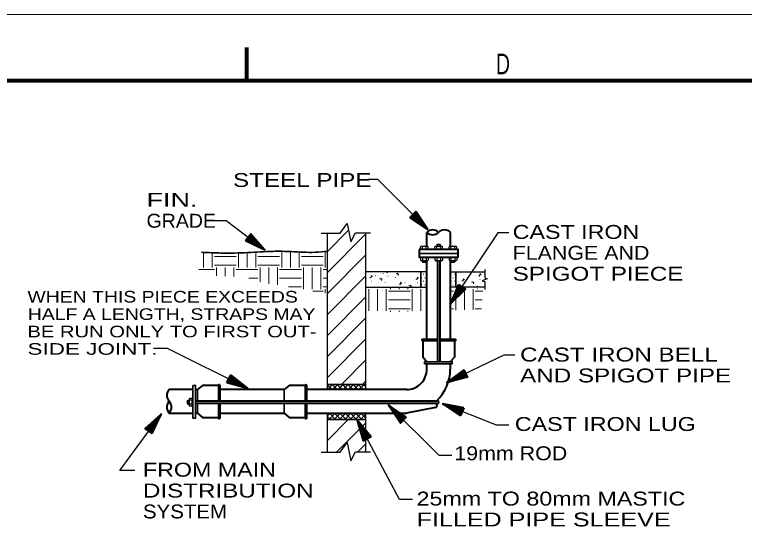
# Model space of a CAD drawing. Extents: x 55 to 190, y 198 to 264.
# Drawn here: x 89.01 to 102.33, y 248.35 to 257.85 of the extents above; entities that cross this region are included whole.
import ezdxf
from ezdxf.enums import TextEntityAlignment as Align

# ---------------------------------------------------------------- set-up
doc = ezdxf.new("R2010")
doc.units = 0
doc.header["$LTSCALE"] = 0.1
doc.layers.add('1', color=7, linetype='Continuous', lineweight=25)
doc.layers.add('2', color=7, linetype='Continuous', lineweight=40)

msp = doc.modelspace()

# ---------------------------------------------------------------- linework, layer by layer
at = {"layer": '1', "lineweight": 80}
msp.add_line((93.2427, 257.2525), (93.2427, 256.6525), dxfattribs=at)
at = {"layer": '1', "lineweight": 13}
msp.add_lwpolyline([(62.4915, 257.8525), (146.5927, 257.8525), (146.5927, 198.4512), (62.4915, 198.4512)], close=True, dxfattribs=at)
at = {"layer": '1', "lineweight": 80}
msp.add_lwpolyline([(65.1915, 256.6525), (145.3927, 256.6525), (145.3927, 199.6512), (65.1915, 199.6512)], close=True, dxfattribs=at)
at = {"layer": '2'}
for p, q in [((96.5497, 253.9364), (96.2539, 254.1822)), ((96.5497, 253.9364), (96.2663, 254.1939)), ((96.2788, 254.2066), (96.5497, 253.9364)), ((96.5497, 253.9364), (96.2925, 254.22)), ((96.5497, 253.9364), (96.319, 254.2465)), ((96.5497, 253.9364), (96.2391, 254.1666)), ((93.2729, 253.7928), (93.5769, 253.5602)), ((93.5769, 253.5602), (93.2848, 253.8078)), ((93.5769, 253.5602), (93.3075, 253.8375)), ((96.5354, 253.6266), (96.5354, 253.8803)), ((96.9622, 253.8803), (96.9622, 253.6266)), ((93.5769, 253.5602), (93.239, 253.748)), ((93.5769, 253.5602), (93.2514, 253.7652)), ((93.5769, 253.5602), (93.2623, 253.7785)), ((96.5354, 251.9311), (96.5354, 253.3652)), ((96.7302, 253.3636), (96.7302, 251.5184)), ((96.7802, 251.5184), (96.7802, 253.3636)), ((96.9622, 253.3636), (96.9622, 251.9311)), ((96.9638, 252.5691), (97.1278, 252.9191)), ((96.9638, 252.5691), (97.1461, 252.9077)), ((96.9638, 252.5691), (97.1599, 252.8979)), ((97.1749, 252.8881), (96.9638, 252.5691)), ((96.9638, 252.5691), (97.1908, 252.8773)), ((96.9638, 252.5691), (97.2218, 252.8566)), ((96.5354, 251.385), (96.5354, 251.4845)), ((96.9622, 251.4845), (96.9622, 251.385)), ((93.2631, 251.0387), (92.9453, 251.2586)), ((96.9011, 251.139), (97.221, 251.3562)), ((96.9011, 251.139), (97.2308, 251.3372)), ((96.9011, 251.139), (97.2376, 251.3215)), ((97.2456, 251.3057), (96.9011, 251.139)), ((96.9011, 251.139), (97.2538, 251.2882)), ((96.9011, 251.139), (97.2699, 251.2546)), ((93.2631, 251.0387), (92.8953, 251.1578)), ((93.2631, 251.0387), (92.9043, 251.1771)), ((93.2631, 251.0387), (92.9122, 251.1922)), ((92.9199, 251.2083), (93.2631, 251.0387)), ((93.2631, 251.0387), (92.9286, 251.2252)), ((92.2645, 251.0109), (91.8319, 251.0109)), ((93.9309, 251.0109), (92.7606, 251.0109)), ((96.17, 251.0109), (94.3439, 251.0109)), ((92.3124, 250.8085), (96.7257, 250.8085)), ((96.7257, 250.7553), (92.3151, 250.7553)), ((96.1076, 250.4569), (95.8348, 250.7252)), ((95.8348, 250.7252), (96.1322, 250.4815)), ((95.8348, 250.7252), (96.0677, 250.4167)), ((95.8348, 250.7252), (96.0938, 250.4434)), ((95.8348, 250.7252), (96.12, 250.4696)), ((95.8348, 250.7252), (96.147, 250.4971)), ((97.1815, 250.6096), (96.8257, 250.7503)), ((96.8257, 250.7503), (97.1945, 250.6418)), ((96.8257, 250.7503), (97.1604, 250.5572)), ((96.8257, 250.7503), (97.1741, 250.5918)), ((96.8257, 250.7503), (97.1879, 250.6262)), ((96.8257, 250.7503), (97.2019, 250.6619)), ((91.8319, 250.5839), (92.2645, 250.5839)), ((92.7612, 250.5839), (93.9309, 250.5839)), ((94.3439, 250.5839), (96.1613, 250.5839)), ((96.6955, 250.6879), (96.1613, 250.5839)), ((91.6827, 250.5619), (91.4118, 250.2865)), ((91.6827, 250.5619), (91.4417, 250.2643)), ((91.457, 250.2529), (91.6827, 250.5619)), ((91.6827, 250.5619), (91.4716, 250.2426)), ((91.6827, 250.5619), (91.4851, 250.232)), ((91.6827, 250.5619), (91.5028, 250.2198)), ((95.4499, 250.1113), (95.2702, 250.4492)), ((95.2702, 250.4492), (95.4808, 250.1275)), ((95.2702, 250.4492), (95.3998, 250.0852)), ((95.2702, 250.4492), (95.4329, 250.1026)), ((95.2702, 250.4492), (95.4657, 250.1201)), ((95.2702, 250.4492), (95.4996, 250.1381))]:
    msp.add_line(p, q, dxfattribs=at)
at = {"layer": '2', "lineweight": 13}
for p, q in [((94.7209, 253.5332), (95.1054, 253.9176)), ((94.7212, 253.1501), (95.4178, 253.847)), ((93.888, 253.2414), (93.888, 253.5184)), ((94.0468, 253.2414), (94.0468, 253.5189)), ((94.2055, 253.2414), (94.2055, 253.5216)), ((92.4593, 253.2414), (92.4593, 253.4988)), ((92.618, 253.2414), (92.618, 253.4988)), ((92.6577, 253.4398), (93.0546, 253.4398)), ((93.0943, 253.2414), (93.0943, 253.4946)), ((93.253, 253.2414), (93.253, 253.5028)), ((93.4118, 253.2414), (93.4118, 253.5107)), ((93.4515, 253.4398), (93.8483, 253.4398)), ((94.2452, 253.4398), (94.6421, 253.4398)), ((94.6818, 253.2414), (94.6818, 253.512)), ((94.7212, 252.767), (95.4178, 253.4639)), ((92.6577, 253.2811), (93.0546, 253.2811)), ((93.4515, 253.2811), (93.8483, 253.2811)), ((94.2452, 253.2811), (94.6421, 253.2811)), ((92.3712, 253.2017), (92.6577, 253.2017)), ((92.6974, 253.0858), (92.6974, 253.2414)), ((92.8561, 253.081), (92.8561, 253.2414)), ((93.0149, 253.076), (93.0149, 253.2414)), ((93.0546, 253.2017), (93.4515, 253.2017)), ((93.4911, 252.9805), (93.4911, 253.2414)), ((93.6499, 252.9432), (93.6499, 253.2414)), ((93.8086, 252.9215), (93.8086, 253.2414)), ((93.8483, 253.2017), (94.2452, 253.2017)), ((94.2849, 252.8445), (94.2849, 253.2414)), ((94.4436, 252.8445), (94.4436, 253.2414)), ((94.6024, 252.8445), (94.6024, 253.2414)), ((94.6421, 253.2017), (94.7024, 253.2017)), ((95.7377, 253.1302), (95.7382, 253.1329)), ((95.8007, 253.1498), (95.8311, 253.1591)), ((95.82, 253.1601), (95.8152, 253.1395)), ((96.0044, 253.1353), (95.974, 253.126)), ((95.9901, 253.1334), (96.0131, 253.112)), ((96.0118, 253.0943), (96.019, 253.1252)), ((96.2669, 253.1511), (96.265, 253.153)), ((96.3822, 253.1498), (96.3817, 253.1472)), ((96.4677, 253.1144), (96.4783, 253.1144)), ((96.5312, 253.1144), (96.5317, 253.1144)), ((96.976, 253.1144), (96.9863, 253.1144)), ((97.0392, 253.1144), (97.05, 253.1144)), ((97.1067, 253.1207), (97.1048, 253.1223)), ((97.1556, 253.1559), (97.1569, 253.1615)), ((97.2223, 253.1189), (97.2218, 253.1162)), ((97.5266, 253.1054), (97.5033, 253.1271)), ((97.5811, 253.1186), (97.584, 253.1194)), ((93.2885, 253.0429), (93.4515, 253.0429)), ((93.8483, 253.0429), (94.2452, 253.0429)), ((94.6421, 253.0429), (94.7024, 253.0429)), ((94.7212, 252.3841), (95.4178, 253.0808)), ((95.434, 253.0376), (95.4345, 253.04)), ((95.4972, 253.057), (95.5274, 253.0662)), ((95.5184, 253.0776), (95.5112, 253.0469)), ((95.5432, 253.0736), (95.5202, 253.095)), ((95.5237, 252.9882), (95.521, 252.9874)), ((95.5983, 253.0879), (95.6015, 253.0887)), ((95.7007, 253.0424), (95.6702, 253.0331)), ((95.6864, 253.0405), (95.7094, 253.0189)), ((95.7081, 253.0014), (95.7152, 253.0323)), ((95.8271, 253.081), (95.8248, 253.0802)), ((95.9631, 253.0583), (95.9613, 253.0601)), ((96.0785, 253.057), (96.078, 253.0546)), ((96.274, 253.0064), (96.2746, 253.0091)), ((96.3367, 253.0257), (96.3669, 253.035)), ((96.3584, 253.0466), (96.3513, 253.0157)), ((96.383, 253.0429), (96.3598, 253.0646)), ((96.436, 253.0509), (96.4465, 253.0509)), ((96.4677, 252.9874), (96.4783, 252.9874)), ((96.4995, 253.0509), (96.51, 253.0509)), ((96.5312, 252.9874), (96.532, 252.9874)), ((96.976, 252.9874), (96.9863, 252.9874)), ((97.0075, 253.0509), (97.018, 253.0509)), ((97.0392, 252.9874), (97.05, 252.9874)), ((97.1763, 252.9948), (97.2064, 253.004)), ((97.1985, 253.0157), (97.1913, 252.9847)), ((97.2228, 253.0122), (97.1995, 253.0339)), ((97.2773, 253.0257), (97.2805, 253.0265)), ((97.4178, 253.0683), (97.4183, 253.0707)), ((97.4797, 253.0876), (97.5102, 253.0969)), ((97.5025, 253.1085), (97.4953, 253.0776)), ((97.5062, 253.0189), (97.5038, 253.0181)), ((94.0124, 252.8842), (94.2452, 252.8842)), ((94.6421, 252.8842), (94.7024, 252.8842)), ((95.6594, 252.9651), (95.6575, 252.967)), ((95.7748, 252.9643), (95.7742, 252.9617)), ((95.8724, 252.8445), (95.8724, 252.8691)), ((95.97, 252.9138), (95.9708, 252.9162)), ((96.0311, 252.8445), (96.0311, 252.8704)), ((96.033, 252.9329), (96.0634, 252.9424)), ((96.0547, 252.954), (96.0475, 252.9231)), ((96.0793, 252.9501), (96.056, 252.9715)), ((96.1341, 252.9638), (96.1372, 252.9649)), ((96.1899, 252.8445), (96.1899, 252.8717)), ((96.2367, 252.9186), (96.2063, 252.9093)), ((96.2222, 252.917), (96.2455, 252.8953)), ((96.2447, 252.8794), (96.2513, 252.9085)), ((96.3632, 252.9572), (96.3605, 252.9564)), ((96.436, 252.9239), (96.4465, 252.9239)), ((96.4995, 252.9239), (96.51, 252.9239)), ((97.0075, 252.9239), (97.018, 252.9239)), ((97.1141, 252.9754), (97.1146, 252.9781)), ((97.2027, 252.9262), (97.2001, 252.9255)), ((97.339, 252.904), (97.3371, 252.9059)), ((97.3797, 252.9802), (97.3493, 252.971)), ((97.3657, 252.9794), (97.389, 252.9577)), ((97.3882, 252.9395), (97.3953, 252.9702)), ((97.4549, 252.9022), (97.4543, 252.8995)), ((94.4558, 252.8048), (94.6421, 252.8048)), ((94.6818, 252.7797), (94.6818, 252.8445)), ((95.4337, 252.8048), (95.4358, 252.8048)), ((95.4755, 252.4476), (95.4755, 252.8445)), ((95.6343, 252.4476), (95.6343, 252.8445)), ((95.793, 252.4476), (95.793, 252.8445)), ((95.8327, 252.8048), (96.2296, 252.8048)), ((96.2693, 252.4476), (96.2693, 252.8445)), ((96.428, 252.4476), (96.428, 252.8445)), ((96.9855, 252.8048), (97.0233, 252.8048)), ((97.063, 252.4579), (97.063, 252.8445)), ((97.2218, 252.4638), (97.2218, 252.8445)), ((97.3808, 252.4696), (97.3808, 252.8445)), ((97.4202, 252.8048), (97.5565, 252.8048)), ((97.4599, 252.8445), (97.4599, 252.8471)), ((94.7212, 252.001), (95.4178, 252.6976)), ((95.4337, 252.6461), (95.4358, 252.6461)), ((95.8327, 252.6461), (96.2296, 252.6461)), ((96.9895, 252.6461), (97.0233, 252.6461)), ((97.4202, 252.6461), (97.544, 252.6461)), ((95.4337, 252.4873), (95.4358, 252.4873)), ((95.8327, 252.4873), (96.2296, 252.4873)), ((96.9934, 252.4873), (97.0233, 252.4873)), ((97.4202, 252.4873), (97.5313, 252.4873)), ((95.8724, 252.4283), (95.8724, 252.4476)), ((96.0311, 252.4325), (96.0311, 252.4476)), ((96.1899, 252.4368), (96.1899, 252.4476)), ((94.7215, 251.6179), (95.4178, 252.3143)), ((94.7215, 251.2348), (95.4181, 251.9311)), ((94.9892, 251.1191), (95.4181, 251.548)), ((95.3649, 251.1117), (95.4181, 251.1649)), ((94.7209, 251.0136), (94.8143, 251.1067)), ((94.8053, 251.0109), (94.7212, 251.0948)), ((94.9011, 251.0109), (94.8051, 251.1067)), ((94.8141, 251.0109), (94.9101, 251.1067)), ((94.9969, 251.0109), (94.9008, 251.1067)), ((94.9098, 251.0109), (95.0059, 251.1067)), ((95.0927, 251.0109), (94.9969, 251.1067)), ((95.0059, 251.0109), (95.1017, 251.1067)), ((95.1884, 251.0109), (95.0927, 251.1067)), ((95.1017, 251.0109), (95.1974, 251.1067)), ((95.2842, 251.0109), (95.1884, 251.1067)), ((95.1974, 251.0109), (95.2932, 251.1067)), ((95.38, 251.0109), (95.2842, 251.1067)), ((95.2932, 251.0109), (95.389, 251.1067)), ((95.4178, 251.0686), (95.38, 251.1067)), ((95.389, 251.0109), (95.4178, 251.04)), ((94.7212, 250.5347), (94.7675, 250.581)), ((94.7741, 250.4672), (94.7212, 250.5201)), ((94.7212, 250.0849), (95.1056, 250.4696)), ((94.7495, 250.4672), (94.8633, 250.581)), ((94.8699, 250.4672), (94.7561, 250.581)), ((94.8453, 250.4672), (94.959, 250.581)), ((94.9657, 250.4672), (94.8519, 250.581)), ((94.9411, 250.4672), (95.0548, 250.581)), ((95.0614, 250.4672), (94.9477, 250.581)), ((95.0368, 250.4672), (95.1506, 250.581)), ((95.1572, 250.4672), (95.0435, 250.581)), ((95.1326, 250.4672), (95.2464, 250.581)), ((95.253, 250.4672), (95.1392, 250.581)), ((95.2284, 250.4672), (95.3422, 250.581)), ((95.3488, 250.4672), (95.235, 250.581)), ((95.3242, 250.4672), (95.4178, 250.5609)), ((95.4178, 250.4939), (95.3308, 250.581)), ((94.8945, 249.8751), (95.4181, 250.3987)), ((95.2771, 249.8745), (95.4178, 250.0153))]:
    msp.add_line(p, q, dxfattribs=at)
at = {"layer": '2', "lineweight": 25}
for p, q in [((94.7209, 251.0109), (94.7209, 253.8687)), ((95.4178, 253.8687), (95.4178, 251.0109)), ((96.4206, 253.5673), (96.4206, 253.6158)), ((96.4206, 253.5673), (96.5598, 253.5673)), ((96.4381, 253.6266), (96.5423, 253.6266)), ((96.4553, 253.5673), (96.4553, 253.6158)), ((96.5251, 253.5673), (96.5251, 253.6158)), ((96.5598, 253.5673), (96.5598, 253.6155)), ((96.6825, 253.5673), (96.6825, 253.6158)), ((96.6825, 253.5673), (96.8217, 253.5673)), ((96.7, 253.6266), (96.8043, 253.6266)), ((96.7172, 253.5673), (96.7172, 253.6158)), ((96.7871, 253.5673), (96.7871, 253.6158)), ((96.8217, 253.5673), (96.8217, 253.6155)), ((96.9413, 253.5673), (96.9413, 253.6158)), ((96.9413, 253.5673), (97.0805, 253.5673)), ((96.9588, 253.6266), (97.063, 253.6266)), ((96.976, 253.5673), (96.976, 253.6158)), ((97.0458, 253.5673), (97.0458, 253.6158)), ((97.0805, 253.5673), (97.0805, 253.6155)), ((96.4206, 253.4229), (96.5598, 253.4229)), ((96.4206, 253.4229), (96.4206, 253.3745)), ((96.4553, 253.4229), (96.4553, 253.3745)), ((96.5251, 253.4229), (96.5251, 253.3745)), ((96.5598, 253.4229), (96.5598, 253.3747)), ((96.6825, 253.4229), (96.8217, 253.4229)), ((96.6825, 253.4229), (96.6825, 253.3745)), ((96.7172, 253.4229), (96.7172, 253.3745)), ((96.7871, 253.4229), (96.7871, 253.3745)), ((96.8217, 253.4229), (96.8217, 253.3747)), ((96.9413, 253.4229), (97.0805, 253.4229)), ((96.9413, 253.4229), (96.9413, 253.3745)), ((96.976, 253.4229), (96.976, 253.3745)), ((97.0458, 253.4229), (97.0458, 253.3745)), ((97.0805, 253.4229), (97.0805, 253.3747)), ((96.4381, 253.3636), (96.5423, 253.3636)), ((96.7, 253.3636), (96.8043, 253.3636)), ((96.9588, 253.3636), (97.063, 253.3636)), ((96.5354, 253.1601), (95.4178, 253.1601)), ((96.9622, 253.1601), (97.5903, 253.1601)), ((95.4178, 252.8813), (96.5354, 252.8813)), ((97.5903, 252.8813), (96.9622, 252.8813)), ((92.2542, 250.8503), (92.2061, 250.8503)), ((92.2542, 250.7112), (92.2542, 250.8503)), ((92.1949, 250.7286), (92.1949, 250.8329)), ((92.2542, 250.8157), (92.2058, 250.8157)), ((92.2542, 250.7458), (92.2058, 250.7458)), ((92.2542, 250.7112), (92.2058, 250.7112)), ((94.7209, 249.8724), (94.7209, 250.581)), ((95.4178, 250.581), (95.4178, 249.8724))]:
    msp.add_line(p, q, dxfattribs=at)
at = {"layer": '2', "lineweight": 35}
for p, q in [((97.1072, 253.4951), (96.3949, 253.4951)), ((96.4227, 253.1593), (96.4227, 252.8815)), ((97.0667, 253.1601), (97.0667, 252.8815)), ((96.4558, 251.9311), (96.7302, 251.9311)), ((96.7802, 251.9311), (97.0551, 251.9311)), ((96.4558, 251.9013), (96.7302, 251.9013)), ((96.7802, 251.9013), (97.0551, 251.9013)), ((92.3468, 251.0109), (92.3127, 251.0109)), ((92.3468, 251.0109), (92.3468, 250.8083)), ((92.7297, 251.0906), (92.7297, 250.8064)), ((92.7596, 251.0906), (92.7596, 250.8064)), ((93.9301, 251.0109), (93.9301, 250.8083)), ((94.3129, 251.0906), (94.3129, 250.8085)), ((94.3428, 251.0906), (94.3428, 250.8085)), ((95.4178, 251.1067), (94.7215, 251.1067)), ((92.3468, 250.7553), (92.3468, 250.5823)), ((92.7297, 250.7575), (92.7297, 250.4913)), ((92.7596, 250.7575), (92.7596, 250.4913)), ((93.9301, 250.7553), (93.9301, 250.5823)), ((94.3129, 250.7553), (94.3129, 250.4913)), ((94.3428, 250.7553), (94.3428, 250.4913)), ((92.3468, 250.5836), (92.3127, 250.5836)), ((94.7215, 250.4672), (95.4178, 250.4672))]:
    msp.add_line(p, q, dxfattribs=at)
at = {"layer": '2', "lineweight": 25}
for points in [[(95.4583, 254.8521), (95.634, 254.8521), (96.5497, 253.9364)], [(92.6611, 254.0994), (92.8744, 254.0994), (93.5769, 253.5602)], [(94.6082, 253.8682), (94.9506, 253.8682), (95.0821, 254.0401), (95.1458, 253.7057), (95.235, 253.87), (95.5096, 253.87)], [(98.0301, 253.8737), (97.8292, 253.8737), (96.9638, 252.5691)], [(97.5911, 253.2033), (97.5911, 253.0493), (97.6343, 253.0347), (97.5459, 252.9937), (97.5932, 252.9815), (97.5932, 252.8379)], [(91.5446, 251.7663), (91.7954, 251.7663), (93.2631, 251.0387)], [(98.1428, 251.6409), (97.9422, 251.6409), (96.9011, 251.139)], [(96.9887, 249.8095), (96.763, 249.8095), (95.8348, 250.7252)], [(98.0301, 250.3614), (97.8041, 250.3614), (96.8257, 250.7503)], [(91.2059, 249.5335), (90.93, 249.5335), (91.6827, 250.5619)], [(96.2738, 249.0064), (96.0354, 249.0064), (95.2702, 250.4492)], [(94.6082, 249.8727), (94.9506, 249.8727), (95.0821, 250.0447), (95.1458, 249.7102), (95.235, 249.8745), (95.5096, 249.8745)]]:
    msp.add_lwpolyline(points, dxfattribs=at)
at = {"layer": '2'}
for points in [[(96.2253, 254.1529), (96.3338, 254.2611), (96.5497, 253.9364)], [(96.2253, 254.1529), (96.5497, 253.9364), (96.3058, 254.2336)], [(93.2271, 253.7324), (93.3205, 253.8539), (93.5769, 253.5602)], [(93.2271, 253.7324), (93.5769, 253.5602), (93.2961, 253.8229)], [(97.1117, 252.9299), (97.239, 252.845), (96.9638, 252.5691)], [(97.1117, 252.9299), (96.9638, 252.5691), (97.2067, 252.8672)], [(96.4616, 251.9013), (96.4616, 251.6097), (96.5354, 251.5184)], [(96.9627, 251.5184), (97.0458, 251.6107), (97.0458, 251.9013)], [(92.8866, 251.1403), (92.9548, 251.2774), (93.2631, 251.0387)], [(97.2125, 251.3737), (97.2787, 251.2358), (96.9011, 251.139)], [(97.2125, 251.3737), (96.9011, 251.139), (97.2622, 251.2713)], [(92.8866, 251.1403), (93.2631, 251.0387), (92.9368, 251.2424)], [(92.7297, 251.0847), (92.4381, 251.0847), (92.3468, 251.0109)], [(94.3129, 251.0847), (94.0214, 251.0847), (93.9301, 251.0109)], [(96.1605, 250.5109), (96.0528, 250.4021), (95.8348, 250.7252)], [(96.1605, 250.5109), (95.8348, 250.7252), (96.0809, 250.4296)], [(97.2093, 250.6799), (97.1524, 250.5379), (96.8257, 250.7503)], [(97.2093, 250.6799), (96.8257, 250.7503), (97.1675, 250.5741)], [(92.3468, 250.5836), (92.4392, 250.5005), (92.7297, 250.5005)], [(93.9301, 250.5836), (94.0224, 250.5005), (94.3129, 250.5005)], [(91.5184, 250.2082), (91.3951, 250.2989), (91.6827, 250.5619)], [(91.5184, 250.2082), (91.6827, 250.5619), (91.4263, 250.2754)], [(95.5168, 250.1471), (95.3813, 250.0756), (95.2702, 250.4492)], [(95.5168, 250.1471), (95.2702, 250.4492), (95.4162, 250.0936)]]:
    msp.add_lwpolyline(points, dxfattribs=at)
at = {"layer": '2', "lineweight": 35}
for points in [[(96.781, 253.6269), (96.781, 253.656), (96.7236, 253.656), (96.7236, 253.6269)], [(96.519, 253.3633), (96.519, 253.3342), (96.4616, 253.3342), (96.4616, 253.3633)], [(97.0397, 253.3633), (97.0397, 253.3342), (96.9823, 253.3342), (96.9823, 253.3633)], [(92.1947, 250.8096), (92.1656, 250.8096), (92.1656, 250.7522), (92.1947, 250.7522)]]:
    msp.add_lwpolyline(points, dxfattribs=at)
at = {"layer": '2'}
msp.add_lwpolyline([(96.3939, 253.5644), (96.3939, 253.4279), (97.1072, 253.4279), (97.1072, 253.5644)], close=True, dxfattribs=at)
at = {"layer": '2', "lineweight": 35}
for points in [[(96.4955, 251.5184), (96.4955, 251.4845), (97.0003, 251.4845), (97.0003, 251.5184)], [(92.2645, 251.0892), (92.2645, 250.491), (92.3124, 250.491), (92.3124, 251.0892)]]:
    msp.add_lwpolyline(points, close=True, dxfattribs=at)
at = {"layer": '2'}
for centre, radius, start, end in [((96.6427, 253.7694), 0.1543, 45.9775, 134.02119), ((96.8571, 253.7694), 0.1543, 45.97881, 134.0225), ((96.6427, 253.9913), 0.1543, 225.97881, 314.0225), ((96.1612, 251.385), 0.3742, 269.9847, 360), ((96.1612, 251.385), 0.8011, 313.97386, 0.00182), ((91.9429, 250.9056), 0.1543, 135.97881, 224.0225), ((91.9429, 250.6911), 0.1543, 135.9775, 224.02119), ((91.721, 250.6911), 0.1543, 315.97881, 44.0225), ((96.691, 250.7215), 0.0339, 277.69693, 91.68872), ((96.7257, 250.7819), 0.0266, 270, 90)]:
    msp.add_arc(centre, radius, start, end, dxfattribs=at)
at = {"layer": '2', "lineweight": 25}
for centre, radius, start, end in [((96.4379, 253.6069), 0.0195, 27.8877, 152.03419), ((96.4901, 253.5621), 0.0643, 57.00616, 122.94297), ((96.5423, 253.6068), 0.0195, 26.78269, 151.8391), ((96.6999, 253.6069), 0.0195, 27.8877, 152.03419), ((96.7521, 253.5621), 0.0643, 57.00616, 122.94297), ((96.8043, 253.6068), 0.0195, 26.78269, 151.8391), ((96.9586, 253.6069), 0.0195, 27.8877, 152.03419), ((97.0108, 253.5621), 0.0643, 57.00616, 122.94297), ((97.063, 253.6068), 0.0195, 26.78269, 151.8391), ((96.4379, 253.3833), 0.0195, 207.96581, 332.1123), ((96.4901, 253.4281), 0.0643, 237.05703, 302.99384), ((96.5423, 253.3834), 0.0195, 208.1609, 333.21731), ((96.6999, 253.3833), 0.0195, 207.96581, 332.1123), ((96.7521, 253.4281), 0.0643, 237.05703, 302.99384), ((96.8043, 253.3834), 0.0195, 208.1609, 333.21731), ((96.9586, 253.3833), 0.0195, 207.96581, 332.1123), ((97.0108, 253.4281), 0.0643, 237.05703, 302.99384), ((97.063, 253.3834), 0.0195, 208.1609, 333.21731), ((92.2148, 250.8329), 0.0195, 116.78269, 241.8391), ((92.2146, 250.7285), 0.0195, 117.8877, 242.03419), ((92.2595, 250.7807), 0.0643, 147.00616, 212.94297)]:
    msp.add_arc(centre, radius, start, end, dxfattribs=at)
at = {"layer": '2', "lineweight": 35}
for centre, start, end in [((96.4558, 251.9162), 90, 270), ((97.0551, 251.9162), 270, 90), ((92.7446, 251.0906), 0, 180), ((94.3279, 251.0906), 0, 180), ((92.7446, 250.4913), 180, 0), ((94.3279, 250.4913), 180, 0)]:
    msp.add_arc(centre, 0.0149, start, end, dxfattribs=at)
msp.add_spline([(94.7119, 253.5337), (94.4974, 253.5163), (94.0634, 253.5292), (93.7258, 253.5337), (93.2699, 253.5118), (92.7791, 253.503), (92.4241, 253.5163)], degree=3, dxfattribs=at)

# ---------------------------------------------------------------- texts
at = {"layer": '1', "width": 0.7}
msp.add_text('D', height=0.375, dxfattribs=at).set_placement((97.9255, 256.765), align=Align.CENTER)
at = {"layer": '2'}
for s, height, width, p in [('STEEL PIPE', 0.254, 1.3, (92.9977, 254.7079)), ('FIN. ', 0.254, 1.45, (91.4184, 254.3457)), ('GRADE', 0.254, 1.05, (91.4184, 253.9647)), ('CAST IRON', 0.254, 1.25, (98.102, 253.7605)), ('FLANGE AND', 0.254, 1.15, (98.102, 253.3795)), ('SPIGOT PIECE', 0.254, 1.3, (98.102, 252.9985)), ('WHEN THIS PIECE EXCEEDS', 0.2117, 1.25, (89.2451, 252.6)), ('HALF A LENGTH, STRAPS MAY', 0.2117, 1.25, (89.2514, 252.2825)), ('BE RUN ONLY TO FIRST OUT-', 0.2117, 1.3, (89.2451, 251.965)), ('SIDE JOINT.', 0.2117, 1.45, (89.2451, 251.6475)), ('CAST IRON BELL', 0.254, 1.3, (98.238, 251.5232)), ('AND SPIGOT PIPE', 0.254, 1.3, (98.238, 251.1422)), ('CAST IRON LUG', 0.254, 1.25, (98.1415, 250.2566)), ('19mm ROD', 0.254, 1.15, (97.0363, 249.7227)), ('FROM MAIN ', 0.254, 1.25, (91.3525, 249.4232)), ('DISTRIBUTION', 0.254, 1.3, (91.3525, 249.0422)), ('25mm TO 80mm MASTIC', 0.254, 1.25, (96.3471, 248.8961)), ('SYSTEM', 0.254, 1.1, (91.3525, 248.6611)), ('FILLED PIPE SLEEVE', 0.254, 1.35, (96.3471, 248.5151))]:
    msp.add_text(s, height=height, dxfattribs=dict(at, width=width)).set_placement(p)

doc.saveas('drawing.dxf')
